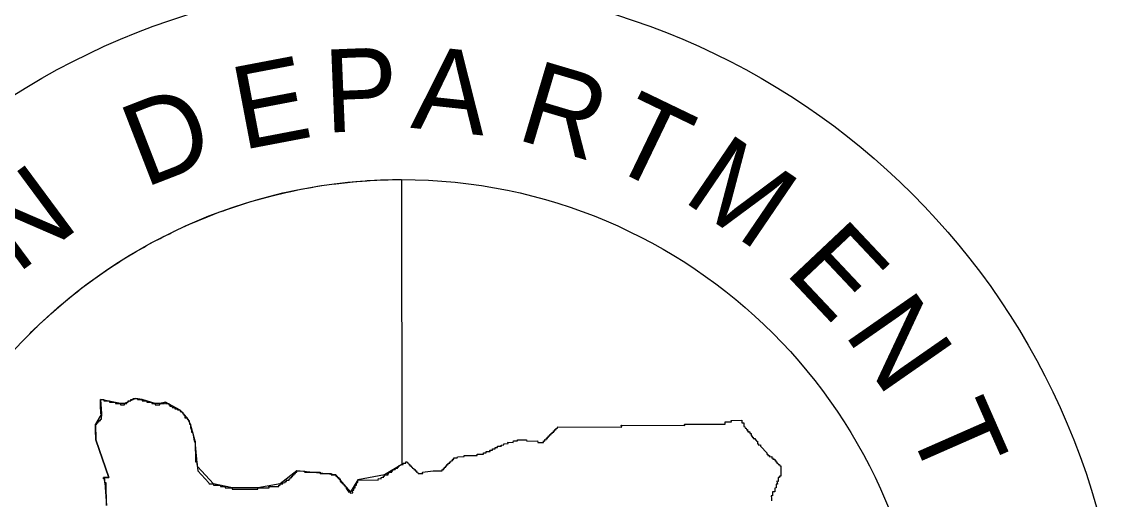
# Model space of a CAD drawing. Extents: x -1.2 to 17.3, y -1 to 2.5.
# Drawn here: x 0.0821 to 0.1583, y 1.9058 to 1.9389 of the extents above; entities that cross this region are included whole.
import ezdxf

# ---------------------------------------------------------------- set-up
doc = ezdxf.new("R2010")
doc.units = 0
doc.layers.add('P_ODOT_PLAN_TBlock', color=7, linetype='Continuous')

msp = doc.modelspace()

# ---------------------------------------------------------------- linework, layer by layer
at = {"layer": 'P_ODOT_PLAN_TBlock'}
for points in [[(0.082008, 1.916744), (0.082346, 1.917094), (0.082606, 1.917357), (0.082753, 1.917503), (0.082982, 1.917728), (0.083079, 1.917821), (0.083095, 1.917837), (0.083119, 1.917861), (0.083284, 1.918019), (0.083514, 1.918234), (0.083804, 1.918503), (0.084059, 1.918734), (0.084617, 1.919223), (0.085402, 1.919881), (0.085778, 1.920182), (0.085993, 1.920351), (0.08621, 1.920519), (0.086696, 1.920885), (0.087028, 1.921128), (0.087884, 1.921728), (0.088431, 1.922093), (0.08862, 1.922216), (0.088739, 1.922292), (0.089002, 1.922459), (0.089118, 1.922532), (0.089964, 1.923042), (0.090461, 1.923328), (0.090648, 1.923433), (0.090685, 1.923454), (0.091147, 1.923707), (0.091619, 1.923954), (0.09182, 1.924058), (0.092261, 1.924279), (0.092391, 1.924343), (0.09253, 1.92441), (0.092579, 1.924434), (0.0926, 1.924443), (0.092607, 1.924447), (0.09285, 1.924562), (0.093652, 1.924928), (0.094006, 1.925082), (0.094275, 1.925196), (0.094619, 1.925338), (0.095287, 1.925603), (0.095762, 1.925782), (0.096001, 1.925869), (0.096241, 1.925954), (0.096653, 1.926097), (0.097067, 1.926234), (0.097906, 1.926497), (0.099376, 1.926904), (0.100311, 1.927128), (0.100667, 1.927207), (0.101362, 1.927351), (0.102066, 1.92748), (0.102516, 1.927556), (0.102967, 1.927626), (0.103674, 1.927724), (0.103772, 1.927737), (0.104588, 1.927831), (0.105158, 1.927885), (0.105488, 1.927913), (0.105517, 1.927915), (0.105596, 1.927921), (0.105816, 1.927937), (0.105938, 1.927945), (0.105985, 1.927948), (0.106454, 1.927975), (0.106618, 1.927984), (0.106884, 1.927995), (0.107393, 1.928013), (0.107711, 1.928019), (0.108121, 1.928024), (0.108267, 1.928024), (0.108333, 1.928024), (0.10834, 1.908308), (0.107157, 1.907593), (0.105301, 1.907232), (0.104809, 1.906419), (0.103791, 1.907585), (0.101086, 1.907854), (0.099936, 1.906954), (0.09839, 1.906684), (0.096631, 1.906686), (0.095318, 1.906956), (0.094205, 1.908175), (0.094049, 1.909919), (0.093716, 1.911084), (0.093482, 1.911535), (0.093005, 1.912073), (0.091986, 1.912612), (0.091607, 1.912522), (0.09127, 1.912523), (0.090378, 1.912792), (0.089909, 1.912881), (0.089146, 1.912523), (0.088875, 1.912523), (0.087499, 1.912792), (0.087554, 1.911805), (0.087149, 1.911084), (0.087163, 1.910012), (0.088061, 1.907396), (0.087702, 1.907404), (0.087794, 1.907045), (0.087899, 1.905462)], [(0.087899, 1.905462), (0.08789, 1.907045), (0.087794, 1.907045), (0.087799, 1.907312), (0.08771, 1.907317), (0.087702, 1.907404), (0.088061, 1.907396), (0.087163, 1.910012), (0.087146, 1.910726), (0.087149, 1.911084), (0.087232, 1.911084), (0.087236, 1.911173), (0.08732, 1.911179), (0.087322, 1.911265), (0.087401, 1.911268), (0.087402, 1.911354), (0.08749, 1.911354), (0.087489, 1.911444), (0.087575, 1.911447), (0.087591, 1.911805), (0.087518, 1.911805), (0.087499, 1.912433), (0.087499, 1.912792), (0.087723, 1.912792), (0.087725, 1.912702), (0.08812, 1.912699), (0.08812, 1.912609), (0.088542, 1.912613), (0.088534, 1.912523), (0.088875, 1.912523), (0.088875, 1.912434), (0.089146, 1.912434), (0.089146, 1.912523), (0.089325, 1.912523), (0.089325, 1.912613), (0.089414, 1.912613), (0.089414, 1.912703), (0.089583, 1.912703), (0.089583, 1.912792), (0.089755, 1.912791), (0.089753, 1.912881), (0.090064, 1.912881), (0.090066, 1.912793), (0.090378, 1.912792), (0.09037, 1.912703), (0.090693, 1.912702), (0.090692, 1.912612), (0.091045, 1.912613), (0.091046, 1.91252), (0.09127, 1.912523), (0.091272, 1.912433), (0.091603, 1.912433), (0.091607, 1.912522), (0.091851, 1.912522), (0.091913, 1.91252), (0.091913, 1.91261), (0.091986, 1.912612), (0.09199, 1.912518), (0.092214, 1.912522), (0.092214, 1.912436), (0.092292, 1.912433), (0.09229, 1.912343), (0.092441, 1.912341), (0.092452, 1.91225), (0.092672, 1.91225), (0.092646, 1.912163), (0.092826, 1.912163), (0.092822, 1.912077), (0.093005, 1.912073), (0.093006, 1.911982), (0.093095, 1.911983), (0.093188, 1.911895), (0.093191, 1.911805), (0.093263, 1.911803), (0.093262, 1.911708), (0.093336, 1.911714), (0.093336, 1.911529), (0.093482, 1.911535), (0.093484, 1.911445), (0.093554, 1.911444), (0.093554, 1.911356), (0.093626, 1.911355), (0.093647, 1.911085), (0.093716, 1.911084), (0.093716, 1.910816), (0.09376, 1.910814), (0.093802, 1.910548), (0.093875, 1.910502), (0.093971, 1.90992), (0.094049, 1.909919), (0.094075, 1.908484), (0.094171, 1.908484), (0.094238, 1.907866), (0.095003, 1.907045), (0.095008, 1.906956), (0.095318, 1.906956), (0.095319, 1.906868), (0.095786, 1.906867), (0.095791, 1.906778), (0.096124, 1.906774), (0.096126, 1.906686), (0.096631, 1.906686), (0.096599, 1.906593), (0.098344, 1.906599), (0.098387, 1.906596), (0.09839, 1.906684), (0.099158, 1.906693), (0.099155, 1.906777), (0.099847, 1.906782), (0.099843, 1.906873), (0.09993, 1.906868), (0.099936, 1.906954), (0.100108, 1.906961), (0.100108, 1.907043), (0.100274, 1.907048), (0.100284, 1.907135), (0.100367, 1.907137), (0.100367, 1.907223), (0.100548, 1.907224), (0.100546, 1.907316), (0.100633, 1.907316), (0.100634, 1.907402), (0.100733, 1.907415), (0.100727, 1.907493), (0.100815, 1.907496), (0.100811, 1.907587), (0.100906, 1.907593), (0.100906, 1.907678), (0.100992, 1.907681), (0.100993, 1.907765), (0.101078, 1.907768), (0.101086, 1.907854), (0.101627, 1.907848), (0.101621, 1.907763), (0.102697, 1.907763), (0.102692, 1.907671), (0.103453, 1.907671), (0.103458, 1.907579), (0.103791, 1.907585), (0.103786, 1.907495), (0.103885, 1.907499), (0.103872, 1.9074), (0.104, 1.907406), (0.103998, 1.907317), (0.104083, 1.907312), (0.104081, 1.907136), (0.104165, 1.907136), (0.104162, 1.907046), (0.104248, 1.907047), (0.104253, 1.906958), (0.104327, 1.906948), (0.10433, 1.906864), (0.104411, 1.906873), (0.104406, 1.906782), (0.104492, 1.906767), (0.104489, 1.906625), (0.104558, 1.906598), (0.104566, 1.90652), (0.104648, 1.90651), (0.104642, 1.906415), (0.104809, 1.906419), (0.104786, 1.906328), (0.10497, 1.906336), (0.104935, 1.906509), (0.105037, 1.906529), (0.105027, 1.906688), (0.105117, 1.906695), (0.105117, 1.906872), (0.105209, 1.906879), (0.105211, 1.907051), (0.105303, 1.907059), (0.105301, 1.907232), (0.106705, 1.907226), (0.106743, 1.907329), (0.106928, 1.907322), (0.10692, 1.907406), (0.107099, 1.907416), (0.107068, 1.907499), (0.107155, 1.907504), (0.107157, 1.907593), (0.107408, 1.907591), (0.107393, 1.907669), (0.107462, 1.907686), (0.107455, 1.907773), (0.107652, 1.907775), (0.107654, 1.907849), (0.10773, 1.90787), (0.107731, 1.907943), (0.1079, 1.907965), (0.107904, 1.908038), (0.108059, 1.90804), (0.108068, 1.908125), (0.108147, 1.90814), (0.108159, 1.908238), (0.108348, 1.90831), (0.108454, 1.908307), (0.108446, 1.908395), (0.108632, 1.908398), (0.108628, 1.908484), (0.108719, 1.908485), (0.108737, 1.908411), (0.108816, 1.908393), (0.108828, 1.908314), (0.108913, 1.908308), (0.108906, 1.908216), (0.108993, 1.908212), (0.108991, 1.908133), (0.109072, 1.908123), (0.109085, 1.90804), (0.109185, 1.908036), (0.109174, 1.90796), (0.109268, 1.907947), (0.109271, 1.907856), (0.109356, 1.907854), (0.109358, 1.907775), (0.109444, 1.907766), (0.109474, 1.907677), (0.109798, 1.907674), (0.109793, 1.907768), (0.110515, 1.907854), (0.11115, 1.907854), (0.111154, 1.907947), (0.111228, 1.907943), (0.11123, 1.908037), (0.111306, 1.908036), (0.111312, 1.908126), (0.111394, 1.908129), (0.11139, 1.908215), (0.111474, 1.908219), (0.111467, 1.908304), (0.111556, 1.908312), (0.111555, 1.908392), (0.11167, 1.908399), (0.11167, 1.908485), (0.111752, 1.908486), (0.111794, 1.908573), (0.111874, 1.908578), (0.111868, 1.908667), (0.111959, 1.908663), (0.111954, 1.908754), (0.112188, 1.908758), (0.112197, 1.908843), (0.112677, 1.908847), (0.112677, 1.908934), (0.113569, 1.908932), (0.113566, 1.909025), (0.114011, 1.909025), (0.114014, 1.90911), (0.114192, 1.909113), (0.114193, 1.909203), (0.114461, 1.909207), (0.11445, 1.909298), (0.114637, 1.909298), (0.114631, 1.90939), (0.114812, 1.909388), (0.1148, 1.909477), (0.114974, 1.909472), (0.114977, 1.909565), (0.115255, 1.909574), (0.115236, 1.909652), (0.115418, 1.909658), (0.115407, 1.909742), (0.115715, 1.909753), (0.115699, 1.909842), (0.116062, 1.909827), (0.11607, 1.909931), (0.116367, 1.909945), (0.116363, 1.910009), (0.116483, 1.910012), (0.116987, 1.910016), (0.116999, 1.909915), (0.117748, 1.909931), (0.117755, 1.90982), (0.118165, 1.909832), (0.118162, 1.909931), (0.118251, 1.909924), (0.118247, 1.910026), (0.11833, 1.910016), (0.118332, 1.910108), (0.118424, 1.910104), (0.118408, 1.910194), (0.118509, 1.910198), (0.118501, 1.91028), (0.118598, 1.910286), (0.118587, 1.910369), (0.118687, 1.910374), (0.118681, 1.910462), (0.118776, 1.910466), (0.118771, 1.91055), (0.118865, 1.910551), (0.11886, 1.910639), (0.118952, 1.91064), (0.118952, 1.910729), (0.119041, 1.910729), (0.119041, 1.910818), (0.119132, 1.910818), (0.119141, 1.91091), (0.123571, 1.910895), (0.123536, 1.911015), (0.127936, 1.911006), (0.127911, 1.91109), (0.130721, 1.911086), (0.130723, 1.911262), (0.131162, 1.911267), (0.131156, 1.911359), (0.131893, 1.911366), (0.131892, 1.91118), (0.132018, 1.911184), (0.132013, 1.910929), (0.132095, 1.910906), (0.132123, 1.910816), (0.132195, 1.910822), (0.132204, 1.910724), (0.132273, 1.910732), (0.132261, 1.91064), (0.132354, 1.910644), (0.132309, 1.910553), (0.132332, 1.910554), (0.132442, 1.910554), (0.132434, 1.910456), (0.132522, 1.91046), (0.132537, 1.91028), (0.132594, 1.910283), (0.1326, 1.91019), (0.132669, 1.910195), (0.132663, 1.910099), (0.132814, 1.910104), (0.132808, 1.910009), (0.132884, 1.910009), (0.132893, 1.909925), (0.132959, 1.909922), (0.132969, 1.909739), (0.133036, 1.909742), (0.133035, 1.909652), (0.133167, 1.909657), (0.133165, 1.909566), (0.133208, 1.90956), (0.133615, 1.909109), (0.133612, 1.909022), (0.13368, 1.909024), (0.13368, 1.908933), (0.133792, 1.908935), (0.133799, 1.908845), (0.133958, 1.908846), (0.133955, 1.908751), (0.134032, 1.90876), (0.134032, 1.908669), (0.134159, 1.908669), (0.134159, 1.908573), (0.134233, 1.908577), (0.13423, 1.908482), (0.13431, 1.908483), (0.134306, 1.908392), (0.13438, 1.908395), (0.134409, 1.908303), (0.134498, 1.908309), (0.134505, 1.908206), (0.13459, 1.908212), (0.13459, 1.907487), (0.134486, 1.907491), (0.134488, 1.907393), (0.134399, 1.907406), (0.134405, 1.907131), (0.13431, 1.90714), (0.134342, 1.906951), (0.134268, 1.906951), (0.134255, 1.906683), (0.134175, 1.906668), (0.134168, 1.90641), (0.134004, 1.906418), (0.134011, 1.906144), (0.133914, 1.906133), (0.133936, 1.905945), (0.13393, 1.905781)]]:
    msp.add_lwpolyline(points, dxfattribs=at)
for radius in [0.05, 0.036358]:
    msp.add_circle((0.108333, 1.891667), radius, dxfattribs=at)

# ---------------------------------------------------------------- texts
for s, rotation, p in [('E', 10.79088, (0.097284, 1.930058)), ('P', 2.30865, (0.103068, 1.931267)), ('A', 353.90454, (0.108912, 1.931612)), ('R', 343.43789, (0.116159, 1.930842)), ('D', 21.21066, (0.090523, 1.927426)), ('T', 334.27595, (0.122297, 1.929096)), ('M', 325.77028, (0.127679, 1.926619)), ('N', 36.51883, (0.081714, 1.921455)), ('E', 313.3114, (0.134764, 1.921622)), ('N', 304.82916, (0.138894, 1.917396)), ('T', 293.72968, (0.143275, 1.911031))]:
    msp.add_text(s, height=0.005739, rotation=rotation, dxfattribs=at).set_placement(p)

doc.saveas('drawing.dxf')
